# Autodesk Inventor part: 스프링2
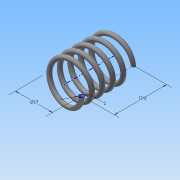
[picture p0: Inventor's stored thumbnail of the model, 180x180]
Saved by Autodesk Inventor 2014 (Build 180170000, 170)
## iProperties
Created: 2016-01
Part Number: 스프링2
Material: 강철, 탄소
Document SubType Name: Modeling
Designer: Administrator
Density: 7.87 g/cm^3
Appearance: 반연마
Mass: 6.44239 g
Surface Area: 16.6857 cm^2
Volume: 0.818602 cm^3
Author: Administrator
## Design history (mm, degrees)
sketch "스케치1"
  geometry: L1 (0, 0)-(8.5, 0); L2 (8.5, 0)-(8.5, 17.5); L3 (8.5, 17.5)-(0, 17.5); L4 (0, 17.5)-(0, 0); C1 r 1 at (8.5, 0)
  constraints: 8 end point, 2 parallel, 1 centre point, 1 coincident, 1 horizontal, 1 perpendicular
  dimensions: "d0" = 17 diameter of L2 L4; "d1" = 17.5 distance of L1.end L2.end (derived); "d2" = 2 diameter of C1
feature "코일1" pitch "d3" = 10; turns "d5" = 5; dims "d4" = 17.5 (= d1), "d6" = 0, angle "d7" = 90 deg, angle "d8" = 90 deg, "d9" = 0, "d10" = 0
node "작업 평면1"
sketch "스케치2"
  geometry: L1 (-9.5, 0)-(-7.5, 0) reference; 1 further point
  constraints: 1 horizontal alignment
extrude "돌출1" cut sketch "스케치2" distance "d12" = 10; taper "d13" = 0 deg
node "작업 평면2"
sketch "스케치3"
  geometry: L1 (-7.5, 0)-(-9.5, 0) reference; 1 further point
  constraints: 1 horizontal alignment
extrude "돌출2" cut sketch "스케치3" distance "d15" = 10; taper "d16" = 0 deg
node "솔리드1"
node "절단 모서리 투영1"
node "절단 모서리 투영2"
other parameters: "d11" = 0, "d14" = 17.5 (= d1)
